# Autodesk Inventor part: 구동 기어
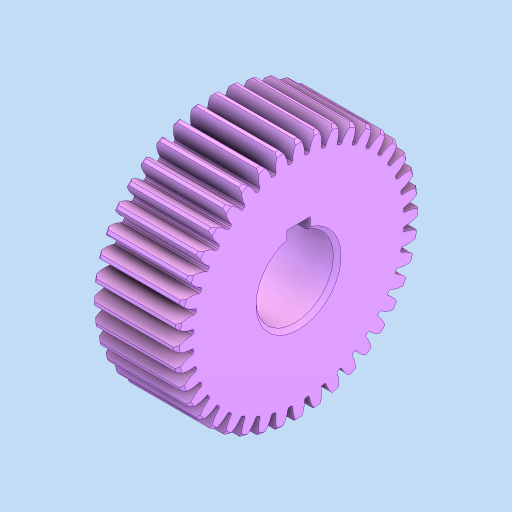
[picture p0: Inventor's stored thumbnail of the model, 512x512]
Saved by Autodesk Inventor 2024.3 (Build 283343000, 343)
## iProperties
Created: 2025-11
Part Number: 구동 기어
Material: 강철, 합금
Document SubType Name: Modeling
Designer: PC2-02
Density: 7.73 g/cm^3
Appearance: 기본값
Author: jhkim
Sending System: Autodesk Inventor 2026
Preprocessor: ST-DEVELOPER v20.1
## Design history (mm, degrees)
node "구동 기어1"
node "솔리드2"
node "솔리드1"
